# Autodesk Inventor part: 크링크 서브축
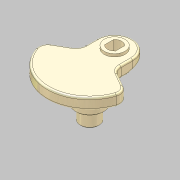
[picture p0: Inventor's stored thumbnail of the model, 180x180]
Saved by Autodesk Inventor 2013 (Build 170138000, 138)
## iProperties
Manager: KYOUNG IL JANG
Company: 한국ATC센터
Created: 2012-10
Part Number: 크링크 서브축
Document SubType Name: Modeling
Density: 1 g/cm^3
Checked By: KYOUNG IL JANG
Vendor: CBT Solutions
Designer: KYOUNG IL JANG
Material: 일반
Author: KYOUNG IL JANG
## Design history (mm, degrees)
sketch "스케치1"
  geometry: L1 (-19, 109.368)-(-19, 91.368); L2 (-19, 91.368)-(-44.545, 76.619); L3 (19, 109.368)-(19, 91.368); L4 (19, 91.368)-(44.545, 76.619); C1 r 32.5 at (0, 83) reference; C2 r 10 at (0, 83); C3 r 17.5 at (0, 83); A1 r 45 centre (0, 83) between (-44.545, 76.619) and (44.545, 76.619); A2 r 32.5 centre (0, 83) between (-19, 109.368) and (19, 109.368); A3 r 19 centre (0, 109.368) between (19, 109.368) and (-19, 109.368); 1 further point
  constraints: 8 end point, 6 point on circle, 5 centre point, 4 coincident, 2 equal length, 1 horizontal alignment, 1 parallel, 1 tangent, 1 vertical, 1 vertical alignment
  dimensions: "d0" = 20 diameter of C2; "d1" = 35 diameter of C3; "d2" = 90 diameter of A1 (derived); "d3" = 65 diameter of A2 (derived); "d4" = 120 deg angle of L3 L4; "d5" = 19 radius of A3 (derived); "d6" = 18 distance of L1.start L1.end (derived)
  node "참조1"
extrude "돌출1" new body sketch "스케치1" distance "d7" = 12; taper "d8" = 0 deg
extrude "돌출2" join sketch "스케치1" distance "d9" = 5; taper "d10" = 0 deg
extrude "돌출3" join sketch "스케치1" distance "d11" = 41; taper "d12" = 0 deg
sketch "스케치2"
  geometry: C1 r 7.5 at (0, 109.368); C2 r 11 at (0, 109.368); A1 r 19 centre (0, 109.368) between (19, 109.368) and (-19, 109.368) reference; 1 further point
  constraints: 2 centre point, 2 coincident
  dimensions: "d13" = 15 diameter of C1; "d14" = 22 diameter of C2
extrude "돌출4" join sketch "스케치2" distance "d15" = 3; taper "d16" = 0 deg
extrude "돌출6" cut sketch "스케치2" stored distance "d19" = 10; taper "d20" = 0 deg
sketch "스케치3"
  geometry: L1 (-5.75, 4.815)-(-5.75, -4.815); L2 (5.75, 4.815)-(5.75, -4.815); A1 r 7.5 centre (0, 0) between (-5.75, 4.815) and (-5.75, -4.815) reference; 1 further point
  constraints: 4 end point, 4 point on circle, 2 parallel, 1 vertical
  dimensions: "d21" = 11.5 distance between parallel lines of L2 L1
extrude "돌출7" join sketch "스케치3" stored distance "d22" = 10; taper "d23" = 0 deg
sketch "스케치4"
  geometry: C1 r 10 at (0, 0) reference; C2 r 15 at (0, 0); 1 further point
  constraints: 1 centre point, 1 coincident
  dimensions: "d30" = 30 diameter of C2
extrude "돌출8" join sketch "스케치4" distance "d28" = 21; taper "d29" = 0 deg
chamfer "모따기1" distance "d31" = 1; stored, may be unused: second distance "d32" = 2, angle "d33" = 45 deg
sketch "스케치5"
  geometry: L1 (-19, 91.368)-(-19, 109.368) reference; L2 (19, 109.368)-(19, 91.368) reference; C1 r 9 at (0, 83); 3 further points
  constraints: 2 point on line, 1 centre point, 1 horizontal alignment
  dimensions: "d34" = 21 vertical distance of point (-19, 104) C1.centre (derived)
node "작업 평면1"
  node "작업축2"
sketch "스케치6"
  geometry: L1 (0, 50)-(38, 50); L2 (38, 50)-(38, 0); L3 (38, 0)-(0, 0); L4 (0, 0)-(0, 50); L5 (0, -12.202)-(0, 5.185) reference; L6 (38, 5.185)-(38, -12.202) reference; 2 further points
  constraints: 8 end point, 2 collinear, 1 point on line
  dimensions: "d37" = 50 distance from line of L1 L3.end
extrude "돌출9" cut sketch "스케치6" stored distance "d38" = 20.7; taper "d39" = 0 deg
fillet "모깎기1" dims "d26" = 10, "d27" = 2
node "솔리드1"
other parameters: "d35" = -15 deg (derived)
